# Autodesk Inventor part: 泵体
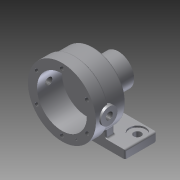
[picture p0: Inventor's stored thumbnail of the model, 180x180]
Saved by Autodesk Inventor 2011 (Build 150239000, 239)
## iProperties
Created: 2013-12
Part Number: 泵体
Document SubType Name: Modeling
Designer: Administrator
Density: 1 g/cm^3
Author: Administrator
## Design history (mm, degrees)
sketch "草图1"
  geometry: L1 (-48, 19)-(48, 19); L2 (48, 19)-(48, -19); L3 (48, -19)-(-48, -19); L4 (-48, -19)-(-48, 19); 3 further points
  constraints: 8 end point, 2 midpoint, 2 parallel, 1 horizontal, 1 horizontal alignment, 1 perpendicular, 1 vertical alignment
  dimensions: "d0" = 96 distance of L1.start L1.end; "d1" = 38 distance of L3.end L1.start
extrude "拉伸1" new body sketch "草图1" distance "d2" = 10; taper "d3" = 0 deg
node "工作平面1"
sketch "草图2"
  geometry: C1 r 41 at (48, 50); 1 further point
  constraints: 1 centre point
  dimensions: "d5" = 82 diameter of C1; "d6" = 50 distance of point (48, 0) C1.centre
extrude "拉伸2" join sketch "草图2" distance "d7" = 16; taper "d8" = 0 deg
sketch "草图3"
  geometry: C1 r 41 at (0, 0) reference; C2 r 39 at (0, 0); 1 further point
  constraints: 1 centre point, 1 coincident
  dimensions: "d9" = 78 diameter of C2
extrude "拉伸3" join sketch "草图3" distance "d10" = 22; taper "d11" = 0 deg
sketch "草图4"
  geometry: C1 r 39 at (0, 0) reference; C2 r 19 at (0, 0); 1 further point
  constraints: 1 centre point, 1 coincident
  dimensions: "d12" = 38 diameter of C2
extrude "拉伸4" join sketch "草图4" distance "d13" = 30; taper "d14" = 0 deg
sketch "草图5"
  geometry: L1 (48, -19)-(-48, -19) reference; L2 (-25, -19)-(25, -19); L3 (25, -19)-(25, -9); L4 (25, -9)-(-25, -9); L5 (-25, -9)-(-25, -19); 2 further points
  constraints: 8 end point, 2 midpoint, 2 parallel, 1 horizontal, 1 perpendicular
  dimensions: "d15" = 50 distance of L3.end L4.end; "d16" = 10 distance of L4.end L2.start
extrude "拉伸5" join sketch "草图5" stored distance "d17" = 40; taper "d18" = 0 deg
sketch "草图6"
  geometry: L1 (-9, 31)-(21, 31) reference; L2 (-19, 10)-(19, 10) reference; L3 (19, 10)-(14, 31); 1 further point
  constraints: 2 end point, 1 point on line
  dimensions: "d19" = 7 distance of L1.end L3.end
feature "加强筋1" sketch "草图6" dims "d20" = 1, "d21" = 10, "d22" = 0
hole "Hole1" diameter "d25" = 9; stored, may be unused: countersink angle "d29" = 90 deg, drill point angle "d31" = 118 deg; dims "d23" = 11, "d24" = 12, "d26" = 6, "d27" = 20, "d28" = 2, "d30" = 8
mirror "镜像1"
hole "Hole2" diameter "d34" = 22; stored, may be unused: countersink angle "d38" = 90 deg, drill point angle "d40" = 146 deg; dims "d32" = 10, "d33" = 10, "d35" = 6, "d36" = 4, "d37" = 2, "d39" = 5
hole "Hole3" diameter "d43" = 15; stored, may be unused: countersink angle "d47" = 90 deg, drill point angle "d49" = 0 deg; dims "d41" = 10, "d42" = 10, "d44" = 6, "d45" = 4, "d46" = 2, "d48" = 5
hole "Hole4" diameter "d52" = 60; stored, may be unused: countersink angle "d56" = 90 deg, drill point angle "d58" = 0 deg; dims "d50" = 10, "d51" = 10, "d53" = 6, "d54" = 4, "d55" = 2, "d57" = 30
chamfer "倒角1" distance "d59" = 1; stored, may be unused: second distance "d60" = 2, angle "d61" = 45 deg
sketch "草图7"
  geometry: C1 r 30 at (0, 0) reference; 2 further points
  dimensions: "d62" = 35 distance of C1.centre point (0, 35)
hole "Hole5" sketch "草图7" at (0, 35) diameter "d63" = 4.917; stored, may be unused: countersink angle "d67" = 90 deg, drill point angle "d69" = 120 deg; dims "d64" = 14, "d65" = 4, "d66" = 2, "d68" = 16
node "工作轴1"
pattern_circular "环形阵列1" dims angle "d71" = 360 deg
sketch "草图8"
  geometry: C1 r 11 at (0, 0) reference; 2 further points
  dimensions: "d73" = 15 distance of C1.centre point (0, 15)
hole "Hole6" sketch "草图8" at (0, 15) diameter "d74" = 3.242; stored, may be unused: countersink angle "d78" = 90 deg, drill point angle "d80" = 120 deg; dims "d75" = 10, "d76" = 4, "d77" = 2, "d79" = 12
pattern_circular "环形阵列2" dims angle "d82" = 360 deg
node "工作平面2"
sketch "草图9"
  geometry: L1 (-47, 9)-(-47, 91) reference; C1 r 10 at (-33, 50); 2 further points
  constraints: 1 centre point, 1 coincident
  dimensions: "d85" = 14 distance from line of L1 point (-33, 50); "d86" = 20 diameter of C1
extrude "拉伸6" join sketch "草图9" stored distance "d87" = 40; taper "d88" = 0 deg
mirror "镜像2"
hole "Hole7" diameter "d91" = 8.566; stored, may be unused: countersink angle "d95" = 90 deg, drill point angle "d97" = 120 deg; dims "d89" = 10, "d90" = 10, "d92" = 10, "d93" = 4, "d94" = 2, "d96" = 12
fillet "圆角1" dims "d98" = 2
fillet "圆角2" dims "d99" = 2
sketch "草图10"
  geometry: 2 further points
hole "Hole8" sketch "草图10" at (17.5, -30.311) diameter "d102" = 2.459; stored, may be unused: countersink angle "d106" = 90 deg, drill point angle "d108" = 120 deg; dims "d103" = 6, "d104" = 4, "d105" = 2, "d107" = 8
node "实体1"
node "工作轴2"
node "工作轴3"
other parameters: "d4" = 28, "d84" = 43
